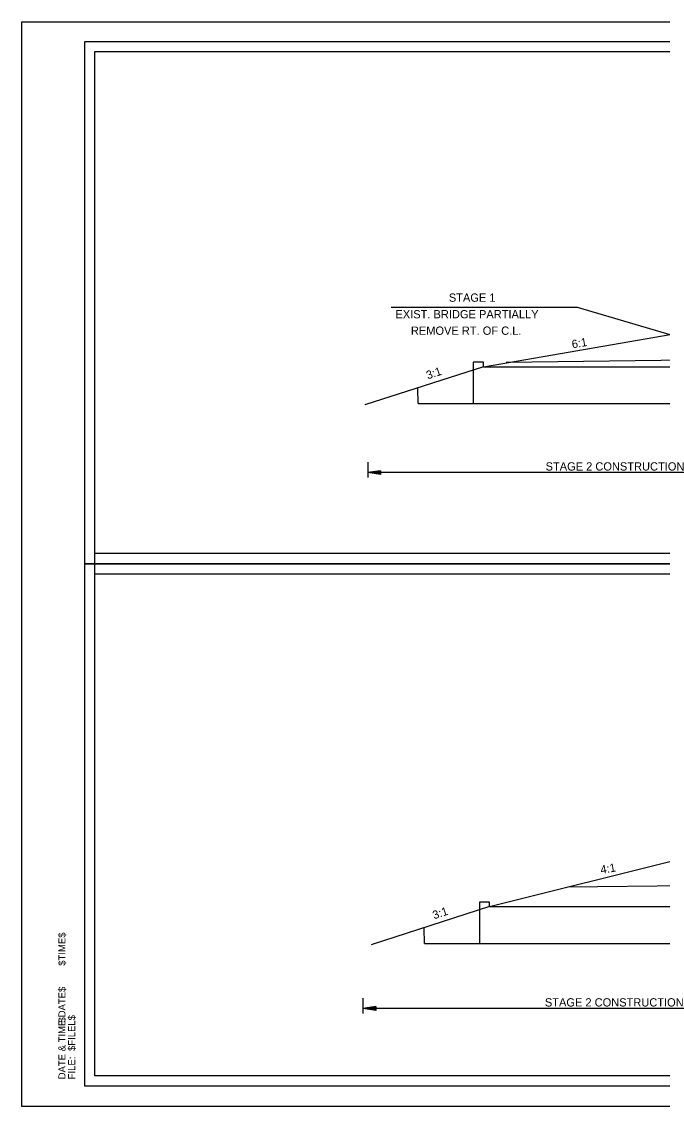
# Model space of a CAD drawing. Extents: x 1368648 to 1927880, y -1037443 to 380209.
# Drawn here: x 1371745 to 1372375, y 378686 to 379753 of the extents above; entities that cross this region are included whole.
import ezdxf

# ---------------------------------------------------------------- set-up
doc = ezdxf.new("R2010")
doc.units = 0
for name, color, linetype in [('Default', 7, 'Continuous'), ('R_Border', 7, 'Continuous'), ('R_Border Notes', 7, 'Continuous'), ('R_Border Plan-Plan', 7, 'Continuous'), ('R_Dimension', 7, 'Continuous'), ('R_Fin Surface', 7, 'Continuous'), ('R_No Plot', 7, 'Continuous'), ('R_Xsect Slope', 7, 'Continuous')]:
    doc.layers.add(name, color=color, linetype=linetype)

msp = doc.modelspace()

# ---------------------------------------------------------------- linework, layer by layer
at = {"layer": 'Default'}
for p, q in [((1372650.7, 379423), (1372221.7, 379417.4)), ((1372199.1, 379417.8), (1372189.2, 379417.8)), ((1372189.2, 379417.8), (1372189.2, 379377.1)), ((1372199.1, 379413.4), (1372199.1, 379417.8)), ((1372199.1, 379413.4), (1372954.2, 379413.5)), ((1372135.1, 379377.1), (1372134.8, 379392.3)), ((1372135.1, 379377.1), (1373018.1, 379377.1)), ((1372657, 378906.2), (1372282.2, 378901.6)), ((1372205.3, 378886.8), (1372195.4, 378886.8)), ((1372195.4, 378886.8), (1372195.4, 378846.1)), ((1372205.3, 378882.4), (1372205.3, 378886.8)), ((1372205.3, 378882.4), (1372960.4, 378882.5)), ((1372141.4, 378846.1), (1372141.1, 378861.3)), ((1372141.4, 378846.1), (1373024.4, 378846.1))]:
    msp.add_line(p, q, dxfattribs=at)
at = {"layer": 'R_Border'}
for p, q in [((1371807.4, 379733.3), (1373388.3, 379733.3)), ((1371807.4, 378706), (1371807.4, 379733.3)), ((1373388.3, 379219.6), (1371807.4, 379219.6)), ((1371807.4, 378706), (1371807.4, 378706)), ((1373388.3, 378706), (1371807.4, 378706))]:
    msp.add_line(p, q, dxfattribs=at)
at = {"layer": 'R_Border Plan-Plan'}
msp.add_line((1371807.4, 379219.6), (1373388.3, 379219.6), dxfattribs=at)
at = {"layer": 'R_Dimension'}
for p, q in [((1372108.6, 379472), (1372291.3, 379472)), ((1372291.3, 379472), (1372413.1, 379436)), ((1372085.5, 379319.4), (1372085.5, 379306.9)), ((1372098, 379311.1), (1372085.5, 379309.3)), ((1372650.7, 379309.3), (1372085.5, 379309.3)), ((1372098, 379307.4), (1372085.5, 379309.3)), ((1372085.5, 379306.9), (1372085.5, 379304.5)), ((1372098, 379310.8), (1372087.6, 379309.3)), ((1372098, 379307.7), (1372087.6, 379309.3)), ((1372098, 379310.5), (1372089.7, 379309.3)), ((1372098, 379308), (1372089.7, 379309.3)), ((1372098, 379310.2), (1372091.8, 379309.3)), ((1372098, 379308.3), (1372091.8, 379309.3)), ((1372098, 379309.9), (1372093.9, 379309.3)), ((1372098, 379308.7), (1372093.9, 379309.3)), ((1372098, 379309.6), (1372096, 379309.3)), ((1372098, 379309), (1372096, 379309.3)), ((1372098, 379311.1), (1372098, 379307.4)), ((1372080.8, 378792.4), (1372080.8, 378779.9)), ((1372093.3, 378784.1), (1372080.8, 378782.2)), ((1372657, 378782.2), (1372080.8, 378782.2)), ((1372093.3, 378780.4), (1372080.8, 378782.2)), ((1372093.3, 378783.8), (1372082.8, 378782.2)), ((1372093.3, 378780.7), (1372082.8, 378782.2)), ((1372093.3, 378783.5), (1372085, 378782.2)), ((1372093.3, 378781), (1372085, 378782.2)), ((1372093.3, 378783.2), (1372087.1, 378782.2)), ((1372093.3, 378781.3), (1372087.1, 378782.2)), ((1372093.3, 378782.8), (1372089.2, 378782.2)), ((1372093.3, 378781.6), (1372089.2, 378782.2)), ((1372093.3, 378782.5), (1372091.3, 378782.2)), ((1372093.3, 378781.9), (1372091.3, 378782.2)), ((1372093.3, 378784.1), (1372093.3, 378780.4)), ((1372080.8, 378779.9), (1372080.8, 378777.4))]:
    msp.add_line(p, q, dxfattribs=at)
at = {"layer": 'R_Fin Surface'}
for p, q in [((1372199.1, 379413.4), (1372392.2, 379446.8)), ((1372199.1, 379413.4), (1372082.5, 379375.9)), ((1372205.3, 378882.4), (1372395.4, 378930)), ((1372205.3, 378882.4), (1372088.7, 378844.9))]:
    msp.add_line(p, q, dxfattribs=at)
at = {"layer": 'R_No Plot'}
for points in [[(1371745.4, 379752.7), (1373412.1, 379752.7), (1373412.1, 378686), (1371745.4, 378686)], [(1373378.3, 379229.6), (1371817.4, 379229.6), (1371817.4, 379723.3), (1373065.1, 379723.3), (1373065.1, 379673.9), (1373152.8, 379673.9), (1373273.3, 379673.9), (1373273.3, 379562.2), (1373378.3, 379562.2)], [(1371817.4, 379723.3), (1373065.1, 379723.3), (1373065.1, 379673.9), (1373152.8, 379673.9), (1373273.3, 379673.9), (1373273.3, 379562.2), (1373378.3, 379562.2), (1373378.3, 378716), (1371817.4, 378716)], [(1371817.4, 379209.6), (1373378.3, 379209.6), (1373378.3, 378716), (1371817.4, 378716)]]:
    msp.add_lwpolyline(points, close=True, dxfattribs=at)

# ---------------------------------------------------------------- texts
at = {"layer": 'R_Border Notes'}
for s, height, p in [('$TIME$', 6.98, (1371788.4, 378824.3)), ('$DATE$', 6.98, (1371788.4, 378768.4)), ('DATE & TIME:', 6.984, (1371788.4, 378712.6)), ('$FILEL$', 6.98, (1371798, 378740.5)), ('FILE: ', 6.98, (1371798, 378712.6))]:
    msp.add_text(s, height=height, rotation=90, dxfattribs=at).set_placement(p)
at = {"layer": 'R_Dimension'}
for s, height, p in [('STAGE 1', 8.12, (1372165.2, 379477.3)), ('EXIST. BRIDGE PARTIALLY', 8.125, (1372112.7, 379461)), ('REMOVE RT. OF C.L.', 8.125, (1372127.9, 379444.8)), ('STAGE 2 CONSTRUCTION', 8.125, (1372260.3, 379311.3)), ('STAGE 2 CONSTRUCTION', 8.125, (1372259.6, 378784.2))]:
    msp.add_text(s, height=height, dxfattribs=at).set_placement(p)
at = {"layer": 'R_Xsect Slope'}
for s, rotation, p in [('6:1', 9.4623, (1372286.7, 379431.4)), ('3:1', 18.4349, (1372144.5, 379400.9)), ('4:1', 9.4623, (1372314.9, 378914.6)), ('3:1', 18.4349, (1372150.8, 378869.9))]:
    msp.add_text(s, height=8.12, rotation=rotation, dxfattribs=at).set_placement(p)

doc.saveas('drawing.dxf')
